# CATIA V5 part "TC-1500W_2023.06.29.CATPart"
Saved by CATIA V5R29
Part number: TC-1500W_2023.06.29
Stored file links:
  G:\05_충전기_1.5kW RENEWAL\[고객용 도면]\TC-1500W_2023.06.29.CATPart

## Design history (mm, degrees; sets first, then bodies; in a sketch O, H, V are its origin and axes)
Body1 "Solid1" (main body)
  Solid1: solid without history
